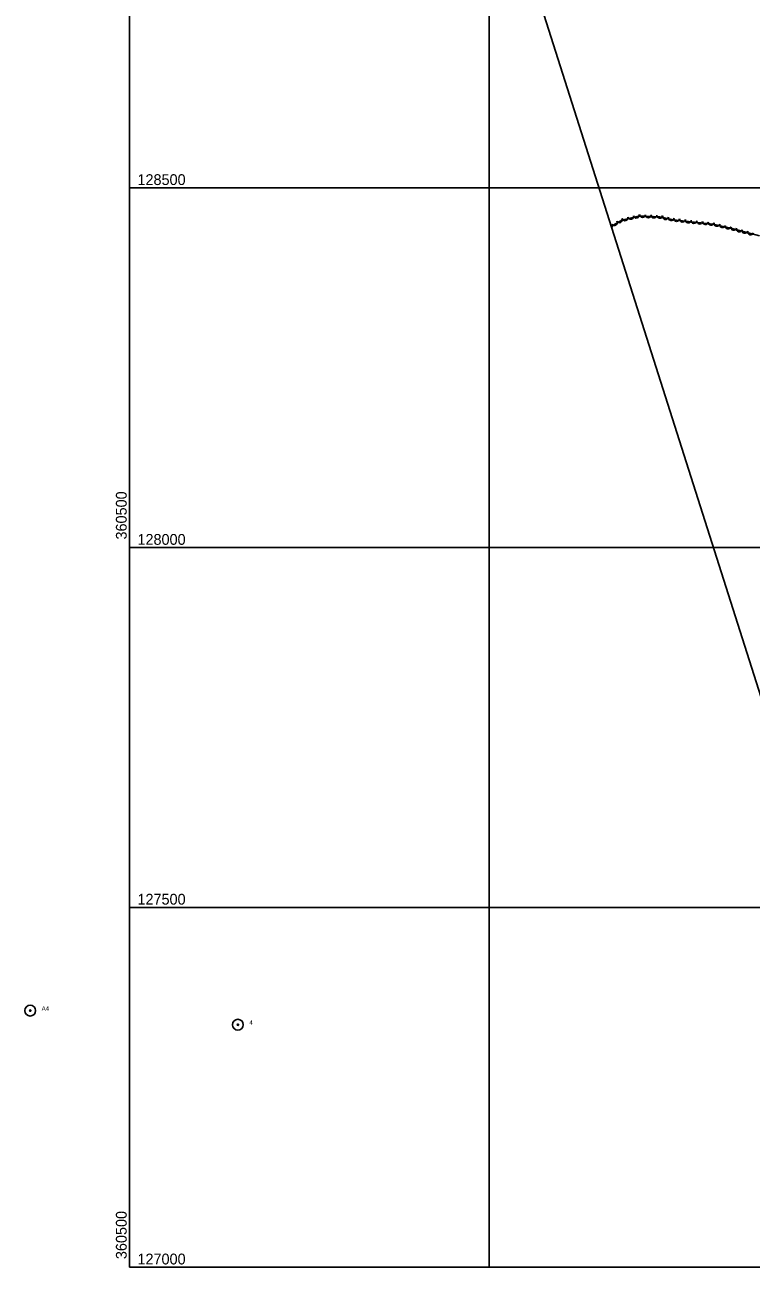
# Model space of a CAD drawing. Extents: x 353423 to 364002, y 127000 to 201942.
# Drawn here: x 360355 to 361364, y 127000 to 128726 of the extents above; entities that cross this region are included whole.
import ezdxf

# ---------------------------------------------------------------- set-up
doc = ezdxf.new("R2010")
doc.units = 0
for name, color, linetype in [('E_FEN_Generic', 7, 'Continuous'), ('E_LAND_TreeLine', 7, 'Continuous'), ('E_RDWY_AsphConc', 7, 'Continuous'), ('E_RDWY_Gravel', 7, 'Continuous')]:
    doc.layers.add(name, color=color, linetype=linetype)

msp = doc.modelspace()

# ---------------------------------------------------------------- linework, layer by layer
at = {"layer": 'E_FEN_Generic'}
msp.add_lwpolyline([(361169.9, 128446.4), (361184.1, 128455), (361209.1, 128460.8), (361237, 128459.5), (361256, 128455.6), (361281.3, 128452.7), (361311.1, 128449.5), (361335.7, 128443.7), (361356.6, 128438.2), (361375.8, 128433.1)], dxfattribs=at)
for centre, start, end in [((361196.7, 128460.1), 193.1066, 13.0913), ((361204.5, 128461.9), 193.1066, 13.0913), ((361213, 128462.7), 177.4296, 357.4143), ((361221, 128462.3), 177.4296, 357.4143), ((361229, 128462), 177.4296, 357.4143), ((361237, 128461.6), 177.4296, 357.4143), ((361245.1, 128460), 168.4766, 348.4613), ((361167.1, 128447.2), 325.0202, 31.0897), ((361173.9, 128451.3), 211.105, 31.0897), ((361180.8, 128455.4), 211.105, 31.0897), ((361188.9, 128458.2), 193.1066, 13.0913), ((361253, 128458.4), 168.4766, 348.4613), ((361260.7, 128457.2), 173.2903, 353.275), ((361268.7, 128456.3), 173.2903, 353.275), ((361276.6, 128455.3), 173.2903, 353.275), ((361284.5, 128454.4), 173.9796, 353.9643), ((361292.5, 128453.6), 173.9796, 353.9643), ((361300.5, 128452.8), 173.9796, 353.9643), ((361308.4, 128451.9), 173.9796, 353.9643), ((361316.5, 128450.4), 166.8082, 346.7929), ((361324.3, 128448.6), 166.8082, 346.7929), ((361332.1, 128446.7), 166.8082, 346.7929), ((361340, 128444.8), 165.087, 345.0717), ((361347.7, 128442.7), 165.087, 345.0717), ((361355.4, 128440.7), 165.087, 345.0717), ((361363.2, 128438.6), 165.2865, 345.2712)]:
    msp.add_arc(centre, 4, start, end, dxfattribs=at)
at = {"layer": 'E_LAND_TreeLine'}
for p, q in [((360500, 127000), (360500, 129500)), ((361000, 127000), (361000, 129500)), ((360500, 128500), (363500, 128500)), ((360500, 128000), (363500, 128000)), ((360500, 127500), (363500, 127500)), ((360500, 127000), (363500, 127000))]:
    msp.add_line(p, q, dxfattribs=at)
at = {"layer": 'E_RDWY_AsphConc'}
for centre, radius in [((360362.1, 127356.5), 7.5), ((360362.1, 127356.5), 0.96), ((360650.7, 127336.9), 7.5), ((360650.7, 127336.9), 0.96)]:
    msp.add_circle(centre, radius, dxfattribs=at)
at = {"layer": 'E_RDWY_Gravel'}
msp.add_lwpolyline([(360907.5, 129271.1), (361478.7, 127475.6)], dxfattribs=at)

# ---------------------------------------------------------------- texts
at = {"layer": 'E_LAND_TreeLine'}
for s, p in [('  128500  ', (360500, 128503.8)), ('  128000  ', (360500, 128003.8)), ('  127500  ', (360500, 127503.8)), ('  127000  ', (360500, 127003.8))]:
    msp.add_text(s, height=15, dxfattribs=at).set_placement(p)
for p in [(360496.2, 128000), (360496.2, 127000)]:
    msp.add_text('  360500  ', height=15, rotation=90, dxfattribs=at).set_placement(p)
at = {"layer": 'E_RDWY_AsphConc'}
for s, p in [('A4', (360378.1, 127356.5)), ('4', (360666.7, 127336.9))]:
    msp.add_text(s, height=6, dxfattribs=at).set_placement(p)

doc.saveas('drawing.dxf')
